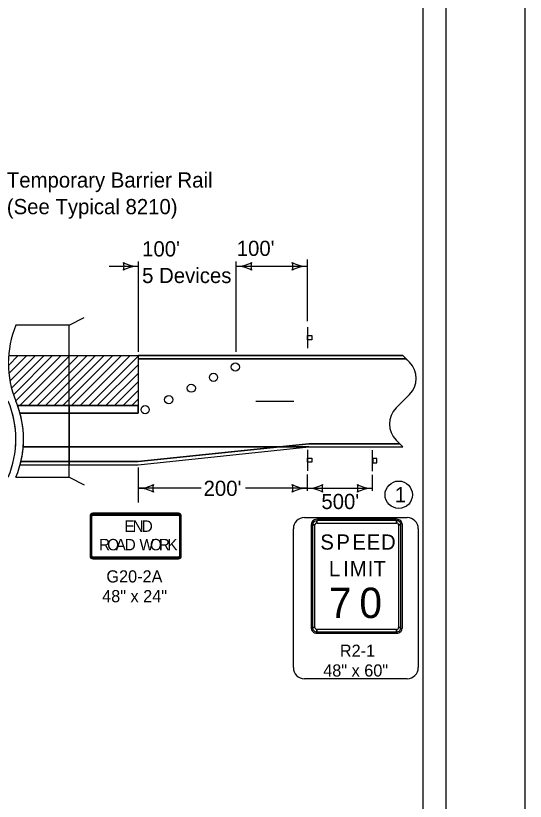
# Model space of a CAD drawing. Extents: x 10133 to 81668, y 4177 to 11018.
# Drawn here: x 27102 to 27772, y 8767 to 9800 of the extents above; entities that cross this region are included whole.
import ezdxf

# ---------------------------------------------------------------- set-up
doc = ezdxf.new("R2010")
doc.units = 0
for name, color, linetype in [('dsnNonPlotable', 7, 'Continuous'), ('dsnShtPlotShapeBatchPrint', 7, 'Continuous'), ('dsnStdBlockModified', 7, 'Continuous'), ('dsnStdBorder', 7, 'Continuous'), ('dsnStdDimension', 7, 'Continuous'), ('dsnStdLabel', 7, 'Continuous'), ('dsnStdNote', 7, 'Continuous'), ('Level 2', 7, 'Continuous'), ('SheetBorder', 7, 'Continuous')]:
    doc.layers.add(name, color=color, linetype=linetype)

msp = doc.modelspace()

# ---------------------------------------------------------------- linework, layer by layer
at = {"layer": 'dsnNonPlotable'}
for p, q in [((27485.6, 9390.6), (27485.6, 9363.1)), ((27092.3, 9340.1), (27105.2, 9353.1)), ((27093, 9329.4), (27116.6, 9353.1)), ((27094.4, 9319.6), (27127.9, 9353.1)), ((27096.4, 9310.3), (27139.2, 9353.1)), ((27099, 9301.6), (27150.5, 9353.1)), ((27102.1, 9293.4), (27161.8, 9353.1)), ((27107.4, 9287.3), (27173.1, 9353.1)), ((27118.7, 9287.3), (27184.4, 9353.1)), ((27130, 9287.3), (27195.8, 9353.1)), ((27141.3, 9287.3), (27207.1, 9353.1)), ((27152.7, 9287.3), (27218.4, 9353.1)), ((27164, 9287.3), (27229.7, 9353.1)), ((27175.3, 9287.3), (27241, 9353.1)), ((27186.6, 9287.3), (27252.3, 9353.1)), ((27197.9, 9287.3), (27263, 9352.4)), ((27263, 9353.1), (27263, 9287.3)), ((27209.2, 9287.3), (27263, 9341.1)), ((27220.5, 9287.3), (27263, 9329.8)), ((27231.8, 9287.3), (27263, 9318.5)), ((27243.2, 9287.3), (27263, 9307.2)), ((27254.5, 9287.3), (27263, 9295.8)), ((27172.2, 9287.3), (27172.2, 9277.3)), ((27263, 9277.3), (27263, 9287.3)), ((27172.2, 9277.3), (27263, 9277.3)), ((27263, 9213.6), (27487.2, 9237.1)), ((27487.2, 9237.1), (27607.1, 9237.1)), ((27485.6, 9229.1), (27485.6, 9201.6)), ((27571.3, 9201.2), (27571.3, 9228.7)), ((27199.7, 9141.9), (27199.7, 9089.4)), ((27200.7, 9141.9), (27202.2, 9141.9)), ((27316, 9145.6), (27203.5, 9145.6)), ((27203.5, 9143.1), (27203.5, 9144.7)), ((27316, 9144.7), (27316, 9143.1)), ((27317.2, 9141.9), (27318.8, 9141.9)), ((27319.7, 9089.4), (27319.7, 9141.9)), ((27490.4, 9130.3), (27490.4, 8995.3)), ((27492.3, 9130.3), (27495.4, 9130.3)), ((27602.9, 9137.8), (27497.9, 9137.8)), ((27497.9, 9132.8), (27497.9, 9136)), ((27602.9, 9136), (27602.9, 9132.8)), ((27605.4, 9130.3), (27608.5, 9130.3)), ((27610.4, 8995.3), (27610.4, 9130.3)), ((27202.2, 9089.4), (27200.7, 9089.4)), ((27203.5, 9086.6), (27203.5, 9088.1)), ((27316, 9088.1), (27316, 9086.6)), ((27318.8, 9089.4), (27317.2, 9089.4)), ((27203.5, 9085.6), (27316, 9085.6)), ((27495.4, 8995.3), (27492.3, 8995.3)), ((27608.5, 8995.3), (27605.4, 8995.3)), ((27497.9, 8989.7), (27497.9, 8992.8)), ((27497.9, 8987.8), (27602.9, 8987.8)), ((27602.9, 8992.8), (27602.9, 8989.7))]:
    msp.add_line(p, q, dxfattribs=at)
for points in [[(27485.7, 9374.1), (27485.7, 9379.8), (27491.3, 9379.8), (27491.3, 9374.1)], [(27485.7, 9212.7), (27485.7, 9218.3), (27491.3, 9218.3), (27491.3, 9212.7)], [(27571.4, 9217.6), (27571.4, 9212), (27577, 9212), (27577, 9217.6)], [(27200.7, 9141.9), (27200.7, 9089.4), (27202.2, 9089.4), (27202.2, 9141.9), (27200.7, 9141.9)], [(27316, 9144.7), (27203.5, 9144.7), (27203.5, 9143.1), (27316, 9143.1), (27316, 9144.7)], [(27318.8, 9089.4), (27318.8, 9141.9), (27317.2, 9141.9), (27317.2, 9089.4), (27318.8, 9089.4)], [(27492.3, 9130.3), (27492.3, 8995.3), (27495.4, 8995.3), (27495.4, 9130.3), (27492.3, 9130.3)], [(27602.9, 9136), (27497.9, 9136), (27497.9, 9132.8), (27602.9, 9132.8), (27602.9, 9136)], [(27608.5, 8995.3), (27608.5, 9130.3), (27605.4, 9130.3), (27605.4, 8995.3), (27608.5, 8995.3)], [(27203.5, 9086.6), (27316, 9086.6), (27316, 9088.1), (27203.5, 9088.1), (27203.5, 9086.6)], [(27497.9, 8989.7), (27602.9, 8989.7), (27602.9, 8992.8), (27497.9, 8992.8), (27497.9, 8989.7)]]:
    msp.add_lwpolyline(points, close=True, dxfattribs=at)
for points in [[(27263, 9287.3), (27254.5, 9287.3), (27243.2, 9287.3), (27231.8, 9287.3), (27220.5, 9287.3), (27209.2, 9287.3), (27197.9, 9287.3), (27186.6, 9287.3), (27175.3, 9287.3), (27172.2, 9287.3)], [(27481.8, 9140), (27616.6, 9140)], [(27467.1, 8942.7), (27467.1, 9125.3)], [(27631.3, 9125.3), (27631.3, 8942.7)], [(27616.6, 8928), (27481.8, 8928)]]:
    msp.add_lwpolyline(points, dxfattribs=at)
for centre in [(27390.7, 9338.1), (27390.7, 9338.1), (27362.1, 9324.5), (27362.1, 9324.5), (27332.8, 9310.2), (27332.8, 9310.2), (27303.2, 9295.1), (27303.2, 9295.1), (27272.2, 9281.9), (27272.2, 9281.9)]:
    msp.add_circle(centre, 5.37, dxfattribs=at)
for centre, radius, start, end in [((27203.5, 9141.9), 3.75, 90.0002, 179.9998), ((27203.5, 9141.9), 2.81, 90.0002, 179.9998), ((27203.5, 9141.9), 1.25, 90.0002, 179.9998), ((27316, 9141.9), 3.75, 0, 90.0002), ((27316, 9141.9), 2.81, 0, 90.0002), ((27316, 9141.9), 1.25, 0, 90.0002), ((27481.8, 9125.3), 14.7, 90, 180), ((27616.6, 9125.3), 14.7, 0, 90), ((27497.9, 9130.3), 7.5, 90.0002, 179.9998), ((27497.9, 9130.3), 5.62, 90.0002, 179.9998), ((27497.9, 9130.3), 2.5, 90.0002, 179.9998), ((27602.9, 9130.3), 7.5, 0, 90.0002), ((27602.9, 9130.3), 5.62, 0, 90.0002), ((27602.9, 9130.3), 2.5, 0, 90.0002), ((27203.5, 9089.4), 3.75, 179.9998, 270.0001), ((27203.5, 9089.4), 2.81, 179.9998, 270.0001), ((27203.5, 9089.4), 1.25, 179.9998, 270.0001), ((27316, 9089.4), 3.75, 270.0001, 0.0003), ((27316, 9089.4), 2.81, 270.0001, 0.0003), ((27316, 9089.4), 1.25, 270.0001, 0.0003), ((27497.9, 8995.3), 7.5, 179.9998, 270.0001), ((27497.9, 8995.3), 5.62, 179.9998, 270.0001), ((27497.9, 8995.3), 2.5, 179.9998, 270.0001), ((27602.9, 8995.3), 7.5, 270.0001, 0.0003), ((27602.9, 8995.3), 5.62, 270.0001, 0.0003), ((27602.9, 8995.3), 2.5, 270.0001, 0.0003), ((27481.8, 8942.7), 14.7, 180, 270), ((27616.6, 8942.7), 14.7, 270, 0)]:
    msp.add_arc(centre, radius, start, end, dxfattribs=at)
at = {"layer": 'dsnShtPlotShapeBatchPrint'}
msp.add_line((27637.5, 9884), (27637.5, 8414), dxfattribs=at)
at = {"layer": 'dsnStdBlockModified'}
msp.add_lwpolyline([(24532.5, 9934), (27667.5, 9934), (27667.5, 7924), (24532.5, 7924)], close=True, dxfattribs=at)
at = {"layer": 'dsnStdBorder'}
msp.add_lwpolyline([(24428, 7819.5), (27772, 7819.5), (27772, 10403.5), (24428, 10403.5)], close=True, dxfattribs=at)
at = {"layer": 'dsnStdDimension'}
for p, q in [((27092.6, 9353.1), (27611.1, 9353.1)), ((27611.1, 9353.1), (27263, 9353.1)), ((27263, 9353.1), (27263, 9349.1)), ((27263, 9349.1), (27615.1, 9349.1)), ((27615.1, 9349.1), (27263, 9349.1)), ((27263, 9349.1), (27263, 9341.1)), ((27615.1, 9349.1), (27611.1, 9353.1)), ((27619.8, 9344.3), (27615.1, 9349.1)), ((27263, 9341.1), (27263, 9329.8)), ((27263, 9329.8), (27263, 9318.5)), ((27602.3, 9284.3), (27619.8, 9301.8)), ((27172.2, 9277.3), (27172.2, 9287.3)), ((27263, 9287.3), (27263, 9277.3)), ((27107.6, 9277.3), (27120.7, 9277.3)), ((27120.7, 9277.3), (27172.2, 9277.3)), ((27172.2, 9233.1), (27172.2, 9277.3)), ((27263, 9277.3), (27172.2, 9277.3)), ((27172.2, 9277.3), (27172.2, 9233.1)), ((27607.1, 9237.1), (27602.3, 9241.8)), ((27172.2, 9233.1), (27111.9, 9233.1)), ((27111.9, 9233.1), (27172.2, 9233.1)), ((27405.4, 9233.1), (27172.2, 9233.1)), ((27172.2, 9233.1), (27172.2, 9213.6)), ((27172.2, 9213.6), (27172.2, 9233.1)), ((27172.2, 9233.1), (27449.1, 9233.1)), ((27263, 9209.6), (27487.2, 9233.1)), ((27263, 9213.6), (27449, 9233.1)), ((27263, 9209.6), (27487.2, 9233.1)), ((27449, 9233.1), (27263, 9213.6)), ((27405.4, 9233.1), (27611.1, 9233.1)), ((27449, 9233.1), (27405.4, 9233.1)), ((27487.2, 9237.1), (27449, 9233.1)), ((27487.2, 9233.1), (27449, 9233.1)), ((27449, 9233.1), (27611.1, 9233.1)), ((27449.1, 9233.1), (27487.2, 9237.1)), ((27607.1, 9237.1), (27487.2, 9237.1)), ((27487.2, 9237.1), (27607.1, 9237.1)), ((27611.1, 9233.1), (27607.1, 9237.1)), ((27108.8, 9213.6), (27121.9, 9213.6)), ((27121.9, 9213.6), (27108.8, 9213.6)), ((27121.9, 9213.6), (27172.2, 9213.6)), ((27172.2, 9213.6), (27121.9, 9213.6)), ((27172.2, 9213.6), (27263, 9213.6)), ((27263, 9213.6), (27172.2, 9213.6)), ((27172.2, 9213.6), (27172.2, 9209.6)), ((27172.2, 9209.6), (27172.2, 9213.6)), ((27107.8, 9209.6), (27172.2, 9209.6)), ((27107.8, 9209.6), (27263, 9209.6)), ((27107.8, 9209.6), (27120.9, 9209.6)), ((27172.2, 9209.6), (27263, 9209.6))]:
    msp.add_line(p, q, dxfattribs=at)
for points in [[(27615.1, 9349.1), (27615.1, 9349.1)], [(27615.1, 9349.1), (27615.1, 9349.1)], [(27263, 9318.5), (27263, 9307.2), (27263, 9295.8), (27263, 9287.3)], [(27172.2, 9287.3), (27164, 9287.3), (27152.7, 9287.3), (27141.3, 9287.3), (27130, 9287.3), (27118.7, 9287.3), (27117.5, 9287.3), (27107.4, 9287.3), (27104.5, 9287.3)], [(27172.2, 9277.3), (27120.7, 9277.3), (27107.6, 9277.3)], [(27405.4, 9233.1), (27405.4, 9233.1)], [(27607.1, 9237.1), (27607.1, 9237.1)], [(27607.1, 9237.1), (27607.1, 9237.1)]]:
    msp.add_lwpolyline(points, dxfattribs=at)
for centre, radius, start, end in [((27598.6, 9323.1), 30, 315, 45), ((26982.2, 9243.1), 130, 15.2832, 19.9082), ((27623.5, 9263.1), 30, 135, 225), ((26972.2, 9243.1), 130, 355.5883, 15.2823), ((26982.2, 9243.1), 130, 355.5892, 15.2832), ((26982.2, 9243.1), 130, 346.8826, 355.5892), ((26982.2, 9243.1), 130, 345.0654, 346.8826)]:
    msp.add_arc(centre, radius, start, end, dxfattribs=at)
at = {"layer": 'dsnStdLabel'}
for p, q in [((27172.2, 9393.1), (27192.2, 9403.1)), ((27619.8, 9344.3), (27611.1, 9353.1)), ((27602.3, 9284.3), (27619.8, 9301.8)), ((27104.5, 9287.3), (27263, 9287.3)), ((27263, 9287.3), (27263, 9277.3)), ((27263, 9277.3), (27107.6, 9277.3)), ((27611.1, 9233.1), (27602.3, 9241.8)), ((27111.9, 9233.1), (27487.2, 9233.1)), ((27263, 9213.6), (27487.2, 9237.1)), ((27108.8, 9213.6), (27263, 9213.6)), ((27102.2, 9193.1), (27172.2, 9193.1)), ((27172.2, 9193.1), (27192.2, 9183.1))]:
    msp.add_line(p, q, dxfattribs=at)
for points in [[(27172.2, 9193.1), (27172.2, 9393.1), (27102.2, 9393.1)], [(27263, 9349.1), (27615.1, 9349.1)], [(27104.5, 9287.3), (27117.5, 9287.3)], [(27417.7, 9293.1), (27467.7, 9293.1)], [(27417.7, 9293.1), (27467.7, 9293.1)], [(27120.7, 9277.3), (27107.6, 9277.3)], [(27487.2, 9237.1), (27607.1, 9237.1)]]:
    msp.add_lwpolyline(points, dxfattribs=at)
for centre, radius, start, end in [((27222.2, 9343.1), 130, 157.3801, 202.6199), ((27598.6, 9323.1), 30, 315, 45), ((26972.2, 9243.1), 130, 337.3801, 22.6199), ((26982.2, 9243.1), 130, 337.3801, 22.6199), ((27623.5, 9263.1), 30, 135, 225)]:
    msp.add_arc(centre, radius, start, end, dxfattribs=at)
at = {"layer": 'dsnStdNote'}
for p, q in [((27485.6, 9398.6), (27485.6, 9479.8)), ((27224.7, 9470.6), (27263.6, 9470.6)), ((27263.5, 9358.1), (27263.5, 9476.8)), ((27392, 9358.1), (27392, 9476.8)), ((27392, 9470.6), (27476.7, 9470.6)), ((27263, 9206.1), (27263, 9159.9)), ((27485.6, 9175.3), (27485.6, 9196.6)), ((27571.3, 9175.3), (27571.3, 9196.3)), ((27345.9, 9178.5), (27263, 9178.5)), ((27485.6, 9178.5), (27404.3, 9178.5)), ((27485.6, 9178.5), (27571.3, 9178.5))]:
    msp.add_line(p, q, dxfattribs=at)
for centre, radius, start, end in [((27228, 9470.6), 16.4, 342.2666, 17.7334), ((27263.6, 9513.1), 42.5, 241.9275, 270), ((27263.6, 9428.1), 42.5, 90, 118.0725), ((27392, 9513.1), 42.5, 270, 298.0725), ((27392, 9428.1), 42.5, 61.9275, 90), ((27427.6, 9470.6), 16.4, 162.2666, 197.7334), ((27450, 9470.6), 16.4, 342.2666, 17.7334), ((27485.7, 9513.1), 42.5, 241.9275, 270), ((27485.7, 9428.1), 42.5, 90, 118.0725), ((27263, 9221), 42.5, 270, 298.0725), ((27298.6, 9178.5), 16.4, 162.2666, 197.7334), ((27450, 9178.5), 16.4, 342.2666, 17.7334), ((27485.6, 9221), 42.5, 241.9275, 270), ((27485.6, 9221), 42.5, 270, 298.0725), ((27521.2, 9178.5), 16.4, 162.2666, 197.7334), ((27535.6, 9178.5), 16.4, 342.2666, 17.7334), ((27571.3, 9221), 42.5, 241.9275, 270), ((27263, 9136), 42.5, 61.9275, 90), ((27485.6, 9136), 42.5, 90, 118.0725), ((27485.6, 9136), 42.5, 61.9275, 90), ((27571.3, 9136), 42.5, 90, 118.0725)]:
    msp.add_arc(centre, radius, start, end, dxfattribs=at)
at = {"layer": 'Level 2'}
msp.add_circle((27605.6, 9170.1), 18, dxfattribs=at)
at = {"layer": 'SheetBorder'}
msp.add_lwpolyline([(24532.5, 9944), (27667.5, 9944), (27667.5, 7924), (24532.5, 7924)], close=True, dxfattribs=at)

# ---------------------------------------------------------------- texts
at = {"layer": 'dsnNonPlotable'}
for s, height, p in [('E', 15, (27245, 9121.2)), ('N', 15, (27255.7, 9121.2)), ('D', 15, (27267.7, 9121.2)), ('S', 20, (27502.5, 9097.8)), ('P', 20, (27523.6, 9097.8)), ('E', 20, (27544.7, 9097.8)), ('E', 20, (27563.5, 9097.8)), ('D', 20, (27582.3, 9097.8)), ('R', 15, (27211.6, 9096.9)), ('O', 15, (27222.3, 9096.9)), ('A', 15, (27233.4, 9096.9)), ('D', 15, (27245.3, 9096.9)), ('W', 15, (27264.7, 9096.9)), ('O', 15, (27278.5, 9096.9)), ('R', 15, (27290.2, 9096.9)), ('K', 15, (27301.5, 9096.9)), ('L', 20, (27513.8, 9062.8)), ('I', 20, (27532.6, 9062.8)), ('M', 20, (27541.2, 9062.8)), ('I', 20, (27564.8, 9062.8)), ('T', 20, (27572.3, 9062.8)), ('G20-2A', 16, (27221.2, 9054.6)), ('7', 40, (27513.8, 9007.8)), ('0', 40, (27553.9, 9007.8)), ('48" x 24"', 16, (27215.6, 9028.6)), ('R2-1', 16, (27528.2, 8956.8)), ('48" x 60"', 16, (27506.3, 8930.8))]:
    msp.add_text(s, height=height, dxfattribs=at).set_placement(p)
at = {"layer": 'dsnStdNote'}
for s, p in [('Temporary Barrier Rail', (27090.3, 9574.2)), ('(See Typical 8210)', (27090.3, 9539.2)), ("100'", (27268.2, 9483.6)), ("100'", (27392.6, 9484.3)), ('5 Devices', (27268.2, 9448.6)), ("200'", (27349, 9168.5)), ("500'", (27503.9, 9151.2))]:
    msp.add_text(s, height=20, dxfattribs=at).set_placement(p)
at = {"layer": 'Level 2'}
msp.add_text('1', height=20, dxfattribs=at).set_placement((27600.4, 9160.1))

doc.saveas('drawing.dxf')
